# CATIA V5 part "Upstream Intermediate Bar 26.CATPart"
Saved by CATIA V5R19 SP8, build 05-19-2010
Part number: Upstream Intermediate Bar 26
Bounding box of the stored display mesh (mm): x -20.5 to 20.5, y 890 to 1008.365, z 390.001 to 508.365
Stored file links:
  G:\EU_thinkMotion\CFAO_2010\MMS_groupe3\MMS_groupe3\A reprendre\fovide\fovide\Upstream Intermediate Bar 26.CATPart
  G:\EU_thinkMotion\CFAO_2010\MMS_groupe3\MMS_groupe3\A reprendre\fovide\fovide\fovide.CATProduct
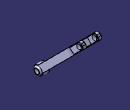
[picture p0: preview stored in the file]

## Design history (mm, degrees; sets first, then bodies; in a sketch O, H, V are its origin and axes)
Set1
  Plane1: linked copy from another document
  Point1 "Point.F": linked copy from another document
  Plane2: linked copy from another document
  Line1 to Line3: linked copy from another document
  Plane3: linked copy from another document
Body1 (main body)
  Sketch1 on Plane1, origin (0, 0, 0), H (0, 1, 0), V (0, 0, 1)
    circle A1 centre (900, 400) radius 10
    point P1 (900, 400)
    reference projected point E1 (900, 400) from Point1
    radius A1 = 10
    coincidence: P1 E1
  Pad1: profile Sketch1, direction (1, 0, 0), length 8, mirrored extent
  Sketch2 on Plane2, origin (0, 250, -250), H (-1, 0, 0), V (0, 0.7071, 0.7071)
    line L1 (-8, 919.2388) -> (8, 919.2388)
    point P1 (-8, 919.2388)
    point P2 (8, 919.2388)
    reference projected line E1 (0, 1060.6602) -> (0, 919.2388) from Line2
    line L2 (12.5, 1068.6602) -> (20.5, 1068.6602)
    line L3 (20.5, 1068.6602) -> (20.5, 1038.6602)
    line L4 (12.5, 1045.3634) -> (12.5, 1068.6602)
    point P5 (20.5, 1038.6602)
    point P7 (-20.5, 1068.6602)
    line L5 (-20.5, 1068.6602) -> (-12.5, 1068.6602)
    line L6 (-12.5, 1068.6602) -> (-12.5, 1045.3634)
    line L7 (-20.5, 1038.6602) -> (-20.5, 1068.6602)
    point P10 (-20.5, 1038.6602)
    reference projected line E2 (150, 1060.6602) -> (-150, 1060.6602) from Line3
    line L8 (-12.5, 1045.3634) -> (12.5, 1045.3634)
    reference projected line E3 (0, 1060.6602) -> (0, 919.2388) from Line2
    reference projected line E4 (150, 919.2388) -> (-150, 919.2388) from Line1
    spline S1 through (8, 919.2388) (8, 929.0978) (8, 947.3188) (8, 959.7029) (8, 972.7063) (8, 983.3559) (8, 1005.1492) (8, 1009.1095) (8, 1012.8718) (14.3207, 1025.3468) (20.5, 1038.6602)
    spline S2 through (-8, 919.2388) (-8, 929.0978) (-8, 947.3188) (-8, 959.7029) (-8, 972.7063) (-8, 983.3559) (-8, 1005.1492) (-8, 1009.1095) (-8, 1012.8718) (-13.966, 1025.3468) (-20.5, 1038.6602)
    point P11 (8, 919.2388)
    point P13 (20.5, 1038.6602)
    point P14 (-8, 919.2388)
    point P15 (-20.5, 1038.6602)
    length L1 = 16
    distance P2 E1 = 8
    distance L2 E2 = 8
    length L2 = 8
    length L8 = 25
    distance L4 E3 = 12.5
    length L5 = 8
    length L3 = 30
    length L7 = 30
    horizontal: L1 H, L2 H, L5 H, L8 H
    vertical: L3 V, L4 V, L6 V, L7 V
    coincidence: P7 L2, L1 E4, P11 P2, P13 P5, P14 P1, P15 P10
  Pad2: profile Sketch2, direction (0, 0.7071, -0.7071), length 7, mirrored extent
  Sketch3 on start face of Pad2, origin (0, 245.0503, -245.0503), H (1, 0, 0), V (0, 0.7071, 0.7071)
    spline S1 through (5.4108, 930.8493) (5.3877, 947.6945) (5.3877, 960.0786) (5.3876, 973.0819) (5.3878, 983.7316) (5.3827, 1005.5249) (5.4018, 1009.4854) (5.4048, 1013.2408) (11.7069, 1025.7197) (17.8878, 1039.0436)
    spline S2 through (-5.9987, 930.8493) (-5.7462, 948.562) (-5.5612, 960.9454) (-5.68, 973.9487) (-5.6248, 984.5984) (-5.6567, 1006.3919) (-5.6189, 1010.3519) (-5.6493, 1014.1141) (-11.6065, 1026.5895) (-17.1219, 1039.0436)
    line L1 (-5.9987, 930.8493) -> (5.3866, 930.8493)
    point P1 (-5.9987, 930.8493)
    line L2 (-17.1219, 1039.0436) -> (17.8878, 1039.0436)
    point P3 (-17.1219, 1039.0436)
    point P4 (17.8878, 1039.0436)
    reference projected curve E1 from edge [start face of Pad2 | face of Pad2]
    reference projected curve E2 from edge [start face of Pad2 | face of Pad2]
    point P5 (-5.9987, 930.8493)
    point P6 (5.4108, 930.8493)
    point P7 (-17.1219, 1039.0436)
    point P8 (17.8878, 1039.0436)
    distance S1 E1 = 2
    distance E2 S2 = 2
    coincidence: P5 P1, L1 P6, P7 P3, P8 P4
    horizontal: L1 H, L2 H
  Sketch4 on end face of Pad2, origin (0, 254.9497, -254.9497), H (-1, 0, 0), V (0, 0.7071, 0.7071)
    spline S1 through (-5.9759, 930.9112) (-5.9739, 948.6338) (-5.9737, 961.0179) (-5.9742, 974.0213) (-5.9733, 984.6709) (-5.9941, 1006.4636) (-5.9713, 1010.4223) (-5.9533, 1014.1874) (-11.9401, 1026.6614) (-17.2682, 1038.9212)
    point P1 (18.0743, 1038.8911)
    point P2 (-17.2682, 1038.9212)
    line L1 (-17.2682, 1038.9212) -> (18.0743, 1038.8911)
    spline S2 through (5.5976, 930.9112) (5.5744, 947.4998) (5.5744, 959.8839) (5.5744, 972.8873) (5.5744, 983.5369) (5.5748, 1005.3301) (5.5727, 1009.2904) (5.5669, 1013.0547) (11.8962, 1025.5282) (18.0743, 1038.8911)
    point P3 (5.5976, 930.9112)
    point P4 (-5.9759, 930.9112)
    line L2 (-5.9759, 930.9112) -> (5.5976, 930.9112)
    reference projected curve E1 from edge [face of Pad2 | end face of Pad2]
    reference projected curve E2 from edge [face of Pad2 | end face of Pad2]
    point P5 (-5.9759, 930.9112)
    point P6 (-17.2682, 1038.9212)
    point P7 (18.0743, 1038.8911)
    point P8 (5.5976, 930.9112)
    distance E1 S2 = 2
    distance S1 E2 = 2
    coincidence: P5 P4, P6 P2, P1 P7, P8 P3
    horizontal: L2 H
  Pocket1: profile Sketch3, direction (0, 0.7071, -0.7071), length 4
  Pocket2: profile Sketch4, direction (0, -0.7071, 0.7071), length 4
  Sketch5 on Plane3, origin (0, 650, 650), H (1, 0, 0), V (0, -0.7071, 0.7071)
    line L1 (8, -344.5534) -> (8, -353.5534)
    point P1 (8, -344.5534)
    line L2 (8, -353.5534) -> (11, -353.5534)
    line L3 (11, -353.5534) -> (11, -347.5534)
    point P4 (11, -347.5534)
    arc A1 centre (3.7393, -351.8141) radius 8.4185 from (11, -347.5534) to (8, -344.5534) ccw
    point P6 (11, -347.5534)
    point P7 (8, -344.5534)
    reference projected line E1 (-150, -353.5534) -> (150, -353.5534) from Line1
    reference projected line E2 (8, -343.5534) -> (8, -363.5534) from edge [face of Pad1 from Sketch1.A1 | end face of Pad1]
    point P8 (-10.8797, -347.5546)
    line L4 (-11, -353.5534) -> (-10.8797, -347.5546)
    point P10 (-10.8797, -347.5546)
    point P11 (-8, -344.5534)
    arc A2 centre (-1.7319, -353.4499) radius 10.8829 from (-8, -344.5534) to (-10.8797, -347.5546) ccw
    point P14 (-8, -344.5534)
    line L5 (-8, -344.5534) -> (-8, -353.5534)
    line L6 (-8, -353.5534) -> (-11, -353.5534)
    reference projected line E3 (-8, -343.5534) -> (-8, -363.5534) from edge [start face of Pad1 | face of Pad1 from Sketch1.A1]
    reference projected line E4 (-150, -353.5534) -> (150, -353.5534) from Line1
    length L3 = 6
    length L2 = 3
    length L1 = 9
    length L5 = 9
    length L4 = 6
    length L6 = 3
    vertical: L1 V, L3 V
    horizontal: L2 H
    coincidence: P7 P1, P6 P4, L2 E1, L1 E2, P11 P14, A2 P8, P10 P8, L5 E3, L6 E4
  Shaft1: profile Sketch5, axis Line1, angle 360
  Sketch6 on face of Shaft1 from Sketch5.L3, origin (11, 900, 400), H (0, 1, 0), V (0, 0, 1)
    point P1 (0, 0)
    intersected point E1 (0, 0) from Line1
    coincidence: E1 P1
  Hole1: placed by Sketch6, at (11, 900, 400) direction (-1, 0, 0), diameter 10, through (limit type 3)
  Sketch7 on face of Pad2 from Sketch2.L7, origin (20.5, 1000, 500), H (0, 1, 0), V (0, 0, 1)
    point P1 (0, 0)
    intersected point E1 (0, 0) from Line3
    coincidence: E1 P1
  Hole2: placed by Sketch7, at (20.5, 1000, 500) direction (-1, 0, 0), diameter 10, through (limit type 3)
  Fillet1: radius 5, on edge [start face of Pad2 | face of Pad2 from Sketch2.L5]; edge [face of Pad2 from Sketch2.L5 | end face of Pad2]; edge [face of Pad2 from Sketch2.L2 | end face of Pad2]; edge [start face of Pad2 | face of Pad2 from Sketch2.L2]
  Fillet2: radius 1, on edge [start face of Pad2 | face of Pad2 from Sketch2.L7]; edge [start face of Pad2 | face of Pad2 from Sketch2.L6]; edge [start face of Pad2 | face of Pad2 from Sketch2.L8]; edge [start face of Pad2 | face of Pad2 from Sketch2.L4]; edge [start face of Pad2 | face of Pad2 from Sketch2.L3]; edge [start face of Pad2 | face of Pocket1]; edge [start face of Pad2 | face of Pocket1 from Sketch3.L2]; edge [face of Pad2 from Sketch2.L7 | end face of Pad2]; edge [face of Pad2 from Sketch2.L6 | end face of Pad2]; edge [face of Pad2 from Sketch2.L8 | end face of Pad2]; edge [face of Pad2 from Sketch2.L4 | end face of Pad2]; edge [face of Pad2 from Sketch2.L3 | end face of Pad2]; edge [end face of Pad2 | face of Pocket2 from Sketch4.L1]; edge [end face of Pad2 | face of Pocket2 from Sketch4.S2]; edge [end face of Pad2 | face of Pocket2 from Sketch4.S1]; edge [end face of Pad2 | face of Pocket2 from Sketch4.L2]; edge [start face of Pad2 | face of Pocket1 from Sketch3.S2]; edge [start face of Pad2 | face of Pocket1 from Sketch3.S1]; end face of Pocket2; end face of Pocket1; face of Pad1 from Sketch1.A1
